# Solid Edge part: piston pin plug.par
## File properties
Author: Robert a Rhodes jr
Template: Normal.par
Last saved by: CADCIM
Revision: 4
Application: Solid Edge
Accuracy: 0.99
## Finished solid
Body 1: solid body, 6 faces, 5 edges, 0 vertices.
  Faces by surface: plane 3, cylinder 2, torus 1
  Edges by curve: circle 5
Bounding box of the edges (mm; curved faces can reach further): 22.000 x 22.000 x 15.000, from (-11, -11, -12) to (11, 11, 3).
Cylindrical faces by radius (mm): R5.5 x1, R11 x1
Toroidal faces (ring radius, tube radius in mm): R9 r2 x1
Planar faces by outward normal: +z 1, -z 2
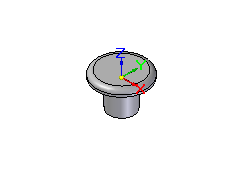
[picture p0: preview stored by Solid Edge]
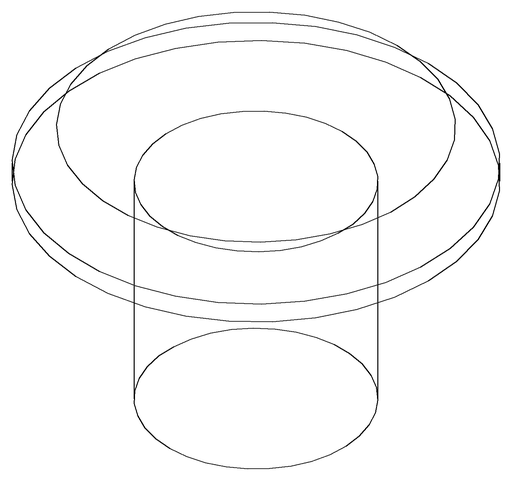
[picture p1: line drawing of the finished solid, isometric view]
